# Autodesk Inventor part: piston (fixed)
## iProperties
Created: 2001-10
Part Number: piston (fixed)
Document SubType Name: Modeling
Designer: hassen
Density: 1 g/cm^3
Control State: 0
Master: False
Checked Out: False
Shininess: 64.0
Length Units: 11269
Angle Units: 11279
Time Units: 11290
Mass Units: 11283
Length Display Precision: 3
Angle Display Precision: 2
Density: 0.0
Volumn: 0.0
Area: 0.0
PropertySet Name: Model Information
Author: hassen
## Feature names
1. Extrusion1
2. Revolution1
3. Revolution2
4. Rectangular Pattern1
5. Extrusion2
6. Extrusion3
7. Mirror1
8. Extrusion6
9. Mirror2
10. Extrusion9
11. Revolution3
12. Extrusion11
13. Mirror3
14. Extrusion12
15. Fillet6
16. Loft1
17. Extrusion13
18. Fillet7
19. Chamfer1
20. Extrusion15
21. Extrusion16
22. Extrusion17
23. Chamfer2
24. Extrusion20
25. Mirror6
26. Chamfer3
